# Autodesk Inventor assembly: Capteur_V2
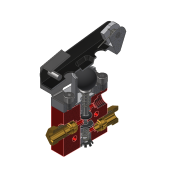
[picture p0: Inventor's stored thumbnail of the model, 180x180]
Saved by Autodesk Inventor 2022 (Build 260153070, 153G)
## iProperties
Created: 2018-06
Part Number: Capteur_V2
Material: Générique
Document SubType Name: Assembly
Designer: Fabian Perrée
Mass: 316.677 g
Surface Area: 499.858 cm^2
Volume: 83.3782 cm^3
Density: 3.79808 g/cm^3
Author: Fabian Perrée
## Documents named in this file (9)
- C:\Users\Fabian\Google Drive\01_Giup\01_Clients\07_ENI\Manuscrit\Fichiers_exercice\Chapitre_06\Exercice_de_fin_de_chapitre\Exercice_fin_de_chapitre_solution\Exercice_fin_de_chapitre_solution.iam
- C:\Users\Fabian\Google Drive\01_Giup\01_Clients\07_ENI\Manuscrit\Fichiers_exercice\Chapitre_06\Exercice_de_fin_de_chapitre\Composants\Capteur.ipt
- C:\Users\Fabian\Google Drive\01_Giup\01_Clients\07_ENI\Manuscrit\Fichiers_exercice\Chapitre_06\Exercice_de_fin_de_chapitre\Exercice_fin_de_chapitre_solution\Ens_cage.iam
- C:\Users\Fabian\Google Drive\01_Giup\01_Clients\07_ENI\Manuscrit\Fichiers_exercice\Chapitre_06\Exercice_de_fin_de_chapitre\Exercice_fin_de_chapitre_solution\Ens_levier.iam
- C:\Users\Fabian\Google Drive\01_Giup\01_Clients\07_ENI\Manuscrit\Fichiers_exercice\Chapitre_06\Exercice_de_fin_de_chapitre\Exercice_fin_de_chapitre_solution\Ens_chapeau.iam
- C:\Users\Fabian\Google Drive\01_Giup\01_Clients\07_ENI\Manuscrit\Fichiers_exercice\Chapitre_06\Exercice_de_fin_de_chapitre\Exercice_fin_de_chapitre_solution\Ens_poussoir.iam
- C:\Users\Fabian\Google Drive\01_Giup\01_Clients\07_ENI\Manuscrit\Fichiers_exercice\Chapitre_06\Exercice_de_fin_de_chapitre\Exercice_fin_de_chapitre_solution\Ens_raccord.iam
- C:\Users\Fabian\Google Drive\01_Giup\01_Clients\07_ENI\Manuscrit\Fichiers_exercice\Chapitre_06\Exercice_de_fin_de_chapitre\Composants\Colle.ipt
- C:\Users\Fabian\Google Drive\01_Giup\01_Clients\07_ENI\Manuscrit\Fichiers_exercice\Chapitre_06\Exercice_de_fin_de_chapitre\Composants\Bille_5-5.ipt
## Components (9 placed, 8 different names)
1. Capteur:1
2. Ens_cage:1 [sub-assembly]
3. Ens_levier:1 [sub-assembly] — Placage:26, Placage:27, Tangente:9, Drive_Me, Placage:30
4. Ens_chapeau:1 [sub-assembly] — Placage:26, Placage:27, Tangente:9, Drive_Me, Placage:30
5. Ens_poussoir:1 [sub-assembly]
6. Ens_raccord:3 [sub-assembly]
7. Ens_raccord:4 [sub-assembly]
8. Colle:1
9. Bille_5-5:1
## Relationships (5: Mate 3, Tangent 1, Angle 1)
- Placage:26 [Mate]: Ens_levier:1 ↔ Ens_chapeau:1
- Placage:27 [Mate]: Ens_levier:1 ↔ Ens_chapeau:1
- Tangente:9: Ens_levier:1 ↔ Ens_chapeau:1
- Drive_Me [Angle]: Ens_levier:1 ↔ Ens_chapeau:1
- Placage:30 [Mate]: Ens_levier:1 ↔ Ens_chapeau:1
